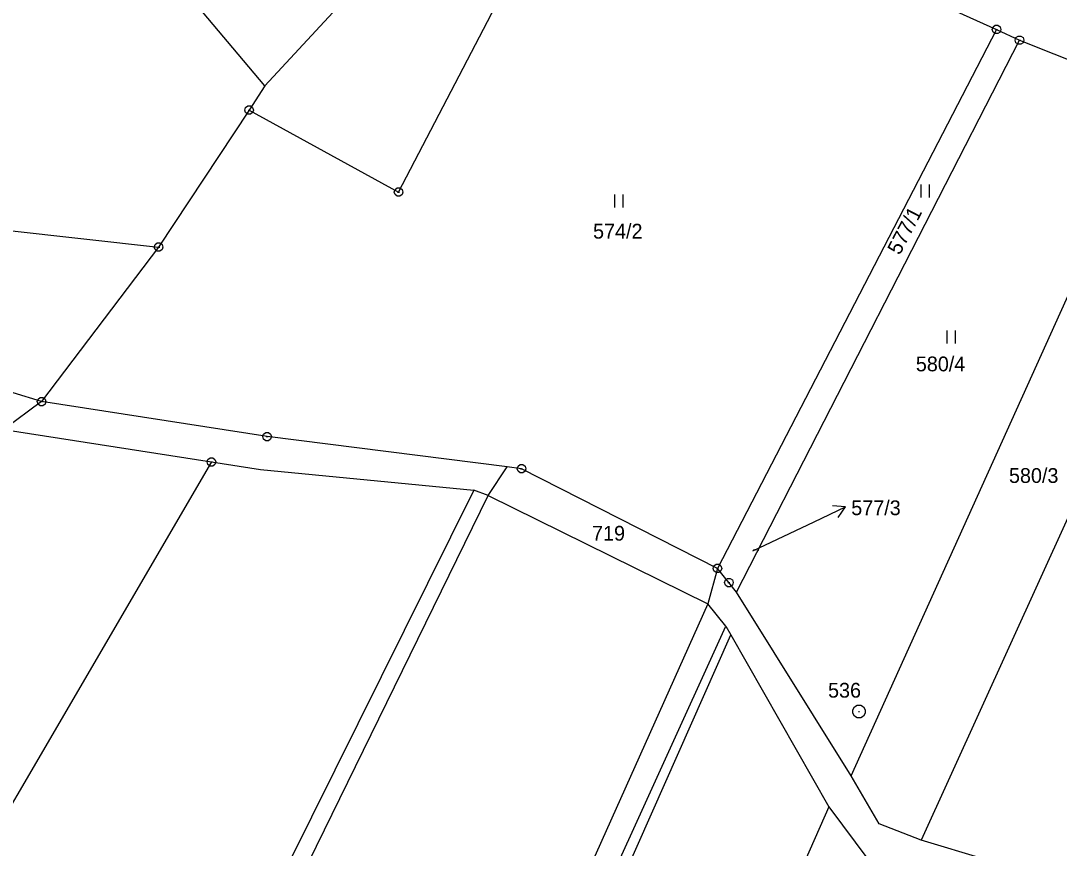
# Model space of a CAD drawing. Extents: x -694465 to -690527, y -983694 to -978978.
# Drawn here: x -692625.8 to -692506.4, y -981699.9 to -981604.7 of the extents above; entities that cross this region are included whole.
import ezdxf

# ---------------------------------------------------------------- set-up
doc = ezdxf.new("R2010")
doc.units = 0
for name, color, linetype in [('Vrstva 1', 7, 'Continuous'), ('Vrstva 16', 7, 'Continuous'), ('Vrstva 17', 7, 'Continuous'), ('Vrstva 18', 7, 'Continuous'), ('Vrstva 24', 7, 'Continuous'), ('Vrstva 25', 7, 'Continuous'), ('Vrstva 29', 7, 'Continuous')]:
    doc.layers.add(name, color=color, linetype=linetype)

msp = doc.modelspace()

# ---------------------------------------------------------------- linework, layer by layer
at = {"layer": 'Vrstva 1'}
for points in [[(-692582.39, -981624.43), (-692561.41, -981584.19)], [(-692561.41, -981584.19), (-692513.61, -981605.72)], [(-692583.58, -981596.88), (-692597.76, -981612.22)], [(-692597.76, -981612.22), (-692606.77, -981601.48)], [(-692513.61, -981605.72), (-692545.72, -981667.72)], [(-692513.61, -981605.72), (-692510.97, -981606.95)], [(-692543.51, -981670.44), (-692510.97, -981606.95)], [(-692510.97, -981606.95), (-692494.98, -981613.3)], [(-692597.76, -981612.22), (-692599.58, -981614.99)], [(-692530.34, -981691.58), (-692494.98, -981613.3)], [(-692599.58, -981614.99), (-692609.99, -981630.75)], [(-692599.58, -981614.99), (-692582.39, -981624.43)], [(-692484.87, -981616.75), (-692522.28, -981698.97)], [(-692636.5, -981627.81), (-692609.99, -981630.75)], [(-692609.99, -981630.75), (-692623.46, -981648.54)], [(-692623.46, -981648.54), (-692639.79, -981643.53)], [(-692623.46, -981648.54), (-692627.78, -981651.76)], [(-692597.51, -981652.56), (-692623.46, -981648.54)], [(-692627.78, -981651.76), (-692603.92, -981655.47)], [(-692569.887, -981656.044), (-692597.51, -981652.56)], [(-692603.92, -981655.47), (-692649.01, -981732.68)], [(-692603.92, -981655.47), (-692598.26, -981656.35)], [(-692598.26, -981656.35), (-692573.72, -981658.74)], [(-692572.08, -981659.34), (-692569.887, -981656.044)], [(-692568.25, -981656.25), (-692569.887, -981656.044)], [(-692545.72, -981667.72), (-692568.25, -981656.25)], [(-692573.72, -981658.74), (-692621.72, -981755.44)], [(-692619.63, -981756.47), (-692572.08, -981659.34)], [(-692572.08, -981659.34), (-692573.72, -981658.74)], [(-692572.08, -981659.34), (-692546.82, -981671.81)], [(-692545.72, -981667.72), (-692546.82, -981671.81)], [(-692544.39, -981669.35), (-692545.72, -981667.72)], [(-692543.51, -981670.44), (-692544.39, -981669.35)], [(-692530.34, -981691.58), (-692543.51, -981670.44)], [(-692546.82, -981671.81), (-692599.203, -981788.767)], [(-692544.75, -981674.36), (-692546.82, -981671.81)], [(-692597.558, -981790.492), (-692544.75, -981674.36)], [(-692544.75, -981674.36), (-692544.18, -981675.36)], [(-692595.935, -981792.193), (-692544.18, -981675.36)], [(-692544.18, -981675.36), (-692532.92, -981695.16)], [(-692527.13, -981697.1), (-692530.34, -981691.58)], [(-692532.92, -981695.16), (-692568.17, -981775.13)], [(-692532.92, -981695.16), (-692528.31, -981701.34)], [(-692522.28, -981698.97), (-692527.13, -981697.1)], [(-692492.68, -981707.89), (-692522.28, -981698.97)]]:
    msp.add_lwpolyline(points, dxfattribs=at)
at = {"layer": 'Vrstva 16'}
msp.add_line((-692541.63, -981665.71), (-692534.6, -981662.36), dxfattribs=at)
at = {"layer": 'Vrstva 24'}
for points in [[(-692513.456, -981605.244), (-692513.206, -981605.426), (-692513.11, -981605.72), (-692513.206, -981606.014), (-692513.456, -981606.196), (-692513.764, -981606.196), (-692514.014, -981606.014), (-692514.11, -981605.72), (-692514.014, -981605.426), (-692513.764, -981605.244)], [(-692513.456, -981605.244), (-692513.206, -981605.426), (-692513.11, -981605.72), (-692513.206, -981606.014), (-692513.456, -981606.196), (-692513.764, -981606.196), (-692514.014, -981606.014), (-692514.11, -981605.72), (-692514.014, -981605.426), (-692513.764, -981605.244)], [(-692510.816, -981606.474), (-692510.566, -981606.656), (-692510.47, -981606.95), (-692510.566, -981607.244), (-692510.816, -981607.426), (-692511.124, -981607.426), (-692511.374, -981607.244), (-692511.47, -981606.95), (-692511.374, -981606.656), (-692511.124, -981606.474)], [(-692510.816, -981606.474), (-692510.566, -981606.656), (-692510.47, -981606.95), (-692510.566, -981607.244), (-692510.816, -981607.426), (-692511.124, -981607.426), (-692511.374, -981607.244), (-692511.47, -981606.95), (-692511.374, -981606.656), (-692511.124, -981606.474)], [(-692599.426, -981614.514), (-692599.176, -981614.696), (-692599.08, -981614.99), (-692599.176, -981615.284), (-692599.426, -981615.466), (-692599.734, -981615.466), (-692599.984, -981615.284), (-692600.08, -981614.99), (-692599.984, -981614.696), (-692599.734, -981614.514)], [(-692599.426, -981614.514), (-692599.176, -981614.696), (-692599.08, -981614.99), (-692599.176, -981615.284), (-692599.426, -981615.466), (-692599.734, -981615.466), (-692599.984, -981615.284), (-692600.08, -981614.99), (-692599.984, -981614.696), (-692599.734, -981614.514)], [(-692582.236, -981623.954), (-692581.986, -981624.136), (-692581.89, -981624.43), (-692581.986, -981624.724), (-692582.236, -981624.906), (-692582.544, -981624.906), (-692582.794, -981624.724), (-692582.89, -981624.43), (-692582.794, -981624.136), (-692582.544, -981623.954)], [(-692609.836, -981630.274), (-692609.586, -981630.456), (-692609.49, -981630.75), (-692609.586, -981631.044), (-692609.836, -981631.226), (-692610.144, -981631.226), (-692610.394, -981631.044), (-692610.49, -981630.75), (-692610.394, -981630.456), (-692610.144, -981630.274)], [(-692609.836, -981630.274), (-692609.586, -981630.456), (-692609.49, -981630.75), (-692609.586, -981631.044), (-692609.836, -981631.226), (-692610.144, -981631.226), (-692610.394, -981631.044), (-692610.49, -981630.75), (-692610.394, -981630.456), (-692610.144, -981630.274)], [(-692623.306, -981648.064), (-692623.056, -981648.246), (-692622.96, -981648.54), (-692623.056, -981648.834), (-692623.306, -981649.016), (-692623.614, -981649.016), (-692623.864, -981648.834), (-692623.96, -981648.54), (-692623.864, -981648.246), (-692623.614, -981648.064)], [(-692623.306, -981648.064), (-692623.056, -981648.246), (-692622.96, -981648.54), (-692623.056, -981648.834), (-692623.306, -981649.016), (-692623.614, -981649.016), (-692623.864, -981648.834), (-692623.96, -981648.54), (-692623.864, -981648.246), (-692623.614, -981648.064)], [(-692597.356, -981652.084), (-692597.106, -981652.266), (-692597.01, -981652.56), (-692597.106, -981652.854), (-692597.356, -981653.036), (-692597.664, -981653.036), (-692597.914, -981652.854), (-692598.01, -981652.56), (-692597.914, -981652.266), (-692597.664, -981652.084)], [(-692603.766, -981654.994), (-692603.516, -981655.176), (-692603.42, -981655.47), (-692603.516, -981655.764), (-692603.766, -981655.946), (-692604.074, -981655.946), (-692604.324, -981655.764), (-692604.42, -981655.47), (-692604.324, -981655.176), (-692604.074, -981654.994)], [(-692568.096, -981655.774), (-692567.846, -981655.956), (-692567.75, -981656.25), (-692567.846, -981656.544), (-692568.096, -981656.726), (-692568.404, -981656.726), (-692568.654, -981656.544), (-692568.75, -981656.25), (-692568.654, -981655.956), (-692568.404, -981655.774)], [(-692545.566, -981667.244), (-692545.316, -981667.426), (-692545.22, -981667.72), (-692545.316, -981668.014), (-692545.566, -981668.196), (-692545.874, -981668.196), (-692546.124, -981668.014), (-692546.22, -981667.72), (-692546.124, -981667.426), (-692545.874, -981667.244)], [(-692544.236, -981668.874), (-692543.986, -981669.056), (-692543.89, -981669.35), (-692543.986, -981669.644), (-692544.236, -981669.826), (-692544.544, -981669.826), (-692544.794, -981669.644), (-692544.89, -981669.35), (-692544.794, -981669.056), (-692544.544, -981668.874)], [(-692529.236, -981683.456), (-692528.9, -981683.65), (-692528.706, -981683.986), (-692528.706, -981684.374), (-692528.9, -981684.71), (-692529.236, -981684.904), (-692529.624, -981684.904), (-692529.96, -981684.71), (-692530.154, -981684.374), (-692530.154, -981683.986), (-692529.96, -981683.65), (-692529.624, -981683.456)]]:
    msp.add_lwpolyline(points, close=True, dxfattribs=at)
for points in [[(-692513.729, -981605.72), (-692513.49, -981605.72)], [(-692513.729, -981605.72), (-692513.49, -981605.72)], [(-692511.089, -981606.95), (-692510.85, -981606.95)], [(-692511.089, -981606.95), (-692510.85, -981606.95)], [(-692599.699, -981614.99), (-692599.46, -981614.99)], [(-692599.699, -981614.99), (-692599.46, -981614.99)], [(-692582.509, -981624.43), (-692582.27, -981624.43)], [(-692610.109, -981630.75), (-692609.87, -981630.75)], [(-692610.109, -981630.75), (-692609.87, -981630.75)], [(-692623.579, -981648.54), (-692623.34, -981648.54)], [(-692623.579, -981648.54), (-692623.34, -981648.54)], [(-692597.629, -981652.56), (-692597.39, -981652.56)], [(-692604.039, -981655.47), (-692603.8, -981655.47)], [(-692568.369, -981656.25), (-692568.13, -981656.25)], [(-692545.839, -981667.72), (-692545.6, -981667.72)], [(-692544.509, -981669.35), (-692544.27, -981669.35)], [(-692529.48, -981684.18), (-692529.38, -981684.18)]]:
    msp.add_lwpolyline(points, dxfattribs=at)
at = {"layer": 'Vrstva 25'}
for points in [[(-692522.33, -981623.56), (-692522.33, -981625.06)], [(-692521.33, -981625.06), (-692521.33, -981623.56)], [(-692557.54, -981624.7), (-692557.54, -981626.2)], [(-692556.54, -981626.2), (-692556.54, -981624.7)], [(-692519.33, -981640.35), (-692519.33, -981641.85)], [(-692518.33, -981641.85), (-692518.33, -981640.35)]]:
    msp.add_lwpolyline(points, dxfattribs=at)
at = {"layer": 'Vrstva 29'}
for points in [[(-692534.6, -981662.36), (-692530.989, -981660.64), (-692532.485, -981660.522)], [(-692531.84, -981661.876), (-692530.989, -981660.64)]]:
    msp.add_lwpolyline(points, dxfattribs=at)

# ---------------------------------------------------------------- texts
at = {"layer": 'Vrstva 16'}
msp.add_text('577/3', height=1.7, dxfattribs=at).set_placement((-692530.323, -981661.6))
at = {"layer": 'Vrstva 17'}
msp.add_text('536', height=1.7, dxfattribs=at).set_placement((-692532.993, -981682.59))
at = {"layer": 'Vrstva 18'}
msp.add_text('577/1', height=1.7, rotation=62.4524, dxfattribs=at).set_placement((-692524.751, -981631.766))
for s, height, p in [('574/2', 1.7, (-692560.023, -981629.78)), ('580/4', 1.7, (-692522.894, -981645.05)), ('580/3', 1.7, (-692512.181, -981657.89)), ('719', 1.7, (-692560.136, -981664.53)), ('577/3', 0.2, (-692541.602, -981665.71))]:
    msp.add_text(s, height=height, dxfattribs=at).set_placement(p)

doc.saveas('drawing.dxf')
